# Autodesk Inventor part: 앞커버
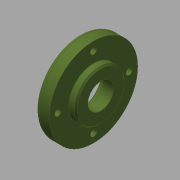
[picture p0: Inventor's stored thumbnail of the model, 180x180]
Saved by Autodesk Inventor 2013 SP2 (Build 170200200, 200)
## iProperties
Created: 2015-12
Part Number: 앞커버
Document SubType Name: Modeling
Designer: mdu
Density: 2.71 g/cm^3
Material: 알루미늄 6061
Author: mdu
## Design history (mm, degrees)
sketch "스케치1"
  geometry: L1 (-7.5, 0)-(7.5, 0); L2 (-7.5, 0)-(-7.5, 31); L3 (-7.5, 31)-(2.5, 31); L4 (2.5, 31)-(2.5, 17.5); L5 (2.5, 17.5)-(7.5, 17.5); L6 (7.5, 17.5)-(7.5, 0); 2 further points
  constraints: 12 end point, 3 perpendicular, 1 coincident, 1 horizontal, 1 midpoint, 1 parallel
  dimensions: "d0" = 15 distance of L1.start L1.end; "d1" = 62 diameter of L3 L1; "d2" = 35 diameter of L5 L1; "d5" = 10 distance of L2.end L3.end
revolve "회전1" sketch "스케치1" stored, may be unused: angle "d6" = 90 deg
sketch "스케치2" dims "d42" = 50
  geometry: 3 further points
  constraints: 2 vertical alignment, 1 coincident, 2 other
hole "구멍1" sketch "스케치2" at (0, 25) diameter "d8" = 4.5; stored, may be unused: countersink angle "d12" = 90 deg, drill point angle "d14" = 118 deg; dims "d9" = 6, "d10" = 8, "d11" = 4.4, "d13" = 8
hole "구멍2" diameter "d20" = 18; stored, may be unused: countersink angle "d24" = 90 deg, drill point angle "d26" = 0 deg; dims "d18" = 10, "d19" = 10, "d21" = 6, "d22" = 8, "d23" = 4.4, "d25" = 8
hole "구멍3" diameter "d34" = 30; stored, may be unused: countersink angle "d38" = 90 deg, drill point angle "d40" = 0 deg; dims "d32" = 10, "d33" = 10, "d35" = 6, "d36" = 4, "d37" = 2, "d39" = 7.3
fillet "모깎기1" dims "d27" = 3, "d41" = 0.3
chamfer "모따기1" distance "d29" = 1; stored, may be unused: second distance "d30" = 2, angle "d31" = 45 deg
node "솔리드1"
pattern_circular "원형 패턴1" dims angle "d16" = 360 deg
